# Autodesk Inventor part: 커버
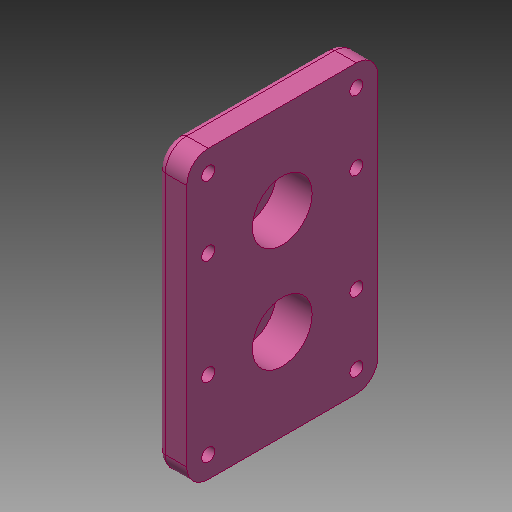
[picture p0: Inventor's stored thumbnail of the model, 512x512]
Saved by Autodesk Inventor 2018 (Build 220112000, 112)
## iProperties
Created: 2019-03
Part Number: 커버
Material: 알루미늄 6061
Document SubType Name: Modeling
Designer: mduedu
Density: 1 g/cm^3
Appearance: 분홍색
Author: mduedu
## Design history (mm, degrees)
sketch "스케치1"
  geometry: L1 (-60, 40)-(60, 40); L2 (60, 40)-(60, -40); L3 (60, -40)-(-60, -40); L4 (-60, -40)-(-60, 40); L5 (-60, 40)-(60, -40); L6 (60, 40)-(-60, -40); 1 further point
  constraints: 12 end point, 2 midpoint, 2 parallel, 1 horizontal, 1 perpendicular
  dimensions: "d59" = 120 distance of L2.end L3.end; "d60" = 80 distance of L1.end L2.end
extrude "돌출1" new body sketch "스케치1" distance "d4" = 12; taper "d5" = 0 deg
sketch "스케치2"
  geometry: L1 (-20, -22)-(20, -22); L2 (20, -22)-(20, 22); L3 (20, 22)-(-20, 22); L4 (-20, 22)-(-20, -22); L5 (-20, -22)-(20, 22); L6 (20, -22)-(-20, 22); 3 further points
  constraints: 12 end point, 4 midpoint, 2 horizontal alignment, 2 parallel, 1 horizontal, 1 perpendicular, 4 other
  dimensions: "d6" = 40 distance between parallel lines of L2 L4; "d8" = 44 distance between parallel lines of L1 L3
extrude "돌출2" join sketch "스케치2" distance "d9" = 10; taper "d10" = 0 deg
fillet "모깎기1" dims "d11" = 9
fillet "모깎기2" dims "d12" = 3
sketch "스케치3"
  geometry: L1 (-31, -60)-(31, -60) reference; L2 (-40, 51)-(-40, -51) reference; L3 (31, 60)-(-31, 60) reference; L4 (40, -51)-(40, 51) reference; L5 (-17, -22)-(-17, 22) reference; L6 (17, 22)-(17, -22) reference; L7 (-31, 51)-(31, 51); L8 (31, 51)-(31, -51); L9 (31, -51)-(-31, -51); L10 (-31, -51)-(-31, 51); A1 r 9 centre (31, -51) between (31, -60) and (40, -51) reference; A2 r 9 centre (-31, -51) between (-40, -51) and (-31, -60) reference; A3 r 9 centre (-31, 51) between (-31, 60) and (-40, 51) reference; A4 r 9 centre (31, 51) between (40, 51) and (31, 60) reference; A5 r 17 centre (0, -22) between (-17, -22) and (17, -22) reference; A6 r 17 centre (0, 22) between (17, 22) and (-17, 22) reference; 9 further points
  constraints: 8 end point, 4 coincident, 4 horizontal alignment, 4 point on line, 2 parallel, 1 horizontal, 1 perpendicular
hole "구멍2" sketch "스케치3" at (-31, 51), (31, 51), (31, -51), (-31, -51), (-31, 22), (-31, -22), (31, 22), (31, -22) diameter "d28" = 5.5; stored, may be unused: countersink angle "d32" = 90 deg, drill point angle "d34" = 118 deg; dims "d29" = 6, "d30" = 4, "d31" = 2, "d33" = 8
sketch "스케치9"
  geometry: L1 (40, -51)-(40, 51) reference; L2 (31, 60)-(-31, 60) reference; L3 (-40, 51)-(-40, -51) reference; L4 (-31, -60)-(31, -60) reference; L5 (23, -22)-(23, 22) reference; L6 (-23, 22)-(-23, -22) reference; C1 r 2.75 at (31, 22) reference; C2 r 2.75 at (-31, 22) reference; C3 r 2.75 at (31, -51) reference; C4 r 2.75 at (-31, 51) reference; C5 r 2.75 at (31, 51) reference; C6 r 2.75 at (-31, -51) reference; C7 r 2.75 at (-31, -22) reference; C8 r 2.75 at (31, -22) reference; A1 r 9 centre (31, -51) between (31, -60) and (40, -51) reference; A2 r 9 centre (31, 51) between (40, 51) and (31, 60) reference; A3 r 9 centre (-31, 51) between (-31, 60) and (-40, 51) reference; A4 r 9 centre (-31, -51) between (-40, -51) and (-31, -60) reference; A5 r 23 centre (0, -22) between (-23, -22) and (23, -22) reference; A6 r 23 centre (0, 22) between (23, 22) and (-23, 22) reference; 9 further points
  constraints: 8 coincident
hole "구멍4" sketch "스케치9" at (-31, 51), (31, 51), (31, 22), (-31, 22), (-31, -22), (31, -22), (31, -51), (-31, -51) diameter "d69" = 11; stored, may be unused: countersink angle "d73" = 90 deg, drill point angle "d75" = 0 deg; dims "d70" = 6, "d71" = 4, "d72" = 2, "d74" = 5.4
fillet "모깎기3" dims "d68" = 3
sketch "스케치6"
  geometry: C1 r 12.5 at (0, 22); 1 further point
  constraints: 1 centre point, 1 vertical alignment
  dimensions: "d43" = 25 diameter of C1; "d45" = 22 distance of C1.centre point (0, 0)
extrude "돌출5" cut sketch "스케치6" distance "d47" = 15; taper "d48" = 0 deg
node "솔리드1"
mirror "대칭1"
node "투영된 루프2"
node "투영된 루프3"
node "투영된 루프4"
